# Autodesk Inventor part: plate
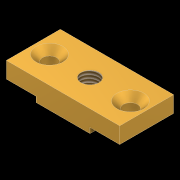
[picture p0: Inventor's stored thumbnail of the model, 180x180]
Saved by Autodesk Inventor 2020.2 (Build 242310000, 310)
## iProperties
Manager: PART
Category: 5
Company: 9
Created: 2020-10
Part Number: plate
Material: Generic
Document SubType Name: Modeling
Designer: Apardo
Density: 1 g/cm^3
Appearance: Brass - Satin
Project: PLATE ROLLING MACHINE
Cost Center: 1
Description: PLATE
Engineer: STEEL C45
Vendor: 5
Stock Number: 1.5
Engr Approved By: D. JAEGER
Author: Apardo
Revision Number: 1.0
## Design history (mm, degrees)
sketch "Sketch1"
  geometry: L1 (21, 10)-(-21, 10); L2 (-21, 10)-(-21, -10); L3 (-21, -10)-(21, -10); L4 (21, -10)-(21, 10); L5 (21, 10)-(-21, -10); L6 (-21, 10)-(21, -10); 1 further point
  constraints: 12 end point, 2 midpoint, 2 parallel, 1 horizontal, 1 perpendicular
  dimensions: "d0" = 20 distance of L1.end L2.end; "d1" = 42 distance of L1.start L1.end
extrude "Extrusion1" new body sketch "Sketch1" stored distance "d2" = 8; taper "d3" = 0 deg
sketch "Sketch2"
  geometry: L1 (21, -10)-(21, 10) reference; L2 (-21, -10)-(21, -10) reference; 2 further points
  dimensions: "d4" = 6 distance from line of L1 point (15, 0); "d5" = 10 distance from line of L2 point (15, 0)
hole "Hole1" sketch "Sketch2" at (15, 0) diameter "d6" = 5.2; stored, may be unused: countersink angle "d10" = 90 deg, drill point angle "d12" = 118 deg; dims "d7" = 6, "d8" = 10, "d9" = 2, "d11" = 8
sketch "Sketch3"
  geometry: L1 (-21, 10)-(-21, -10) reference; L2 (-21, -10)-(21, -10) reference; 2 further points
  dimensions: "d13" = 6 distance from line of L1 point (-15, 0) (= d4); "d14" = 10 distance from line of L2 point (-15, 0) (= d5)
hole "Hole2" sketch "Sketch3" at (-15, 0) diameter "d15" = 5.2; stored, may be unused: countersink angle "d19" = 90 deg, drill point angle "d21" = 118 deg; dims "d16" = 6, "d17" = 10, "d18" = 2, "d20" = 8
sketch "Sketch4"
  geometry: L1 (21, -10)-(21, 10) reference; L2 (-21, -10)-(21, -10) reference; 2 further points
  dimensions: "d22" = 21 distance from line of L1 point (0, 0); "d23" = 10 distance from line of L2 point (0, 0)
hole "Hole3" sketch "Sketch4" at (0, 0) diameter "d24" = 6.647; stored, may be unused: countersink angle "d28" = 90 deg, drill point angle "d30" = 118 deg; dims "d25" = 16, "d26" = 8, "d27" = 2, "d29" = 22.2
sketch "Sketch5"
  geometry: L1 (23, -2)-(10, -2); L2 (10, -2)-(10, -6); L3 (10, -6)-(23, -6); L4 (23, -6)-(23, -2); L5 (-22.476, -2)-(-10, -2); L6 (-10, -2)-(-10, -5); L7 (-10, -5)-(-22.476, -5); L8 (-22.476, -5)-(-22.476, -2); L9 (21, -4)-(21, 4) reference; L10 (21, 4)-(-21, 4) reference; L11 (-21, 4)-(-21, -4) reference; 1 further point
  constraints: 16 end point, 4 parallel, 2 horizontal, 2 perpendicular, 1 point on line
  dimensions: "d31" = 11 distance between parallel lines of L2 L9; "d32" = 6 distance between parallel lines of L10 L1; "d33" = 11 distance between parallel lines of L11 L6 (= d31)
extrude "Extrusion2" cut sketch "Sketch5" extent not by distance; stored distance "d34" = 10; taper "d35" = 0 deg
body "Solid1"
